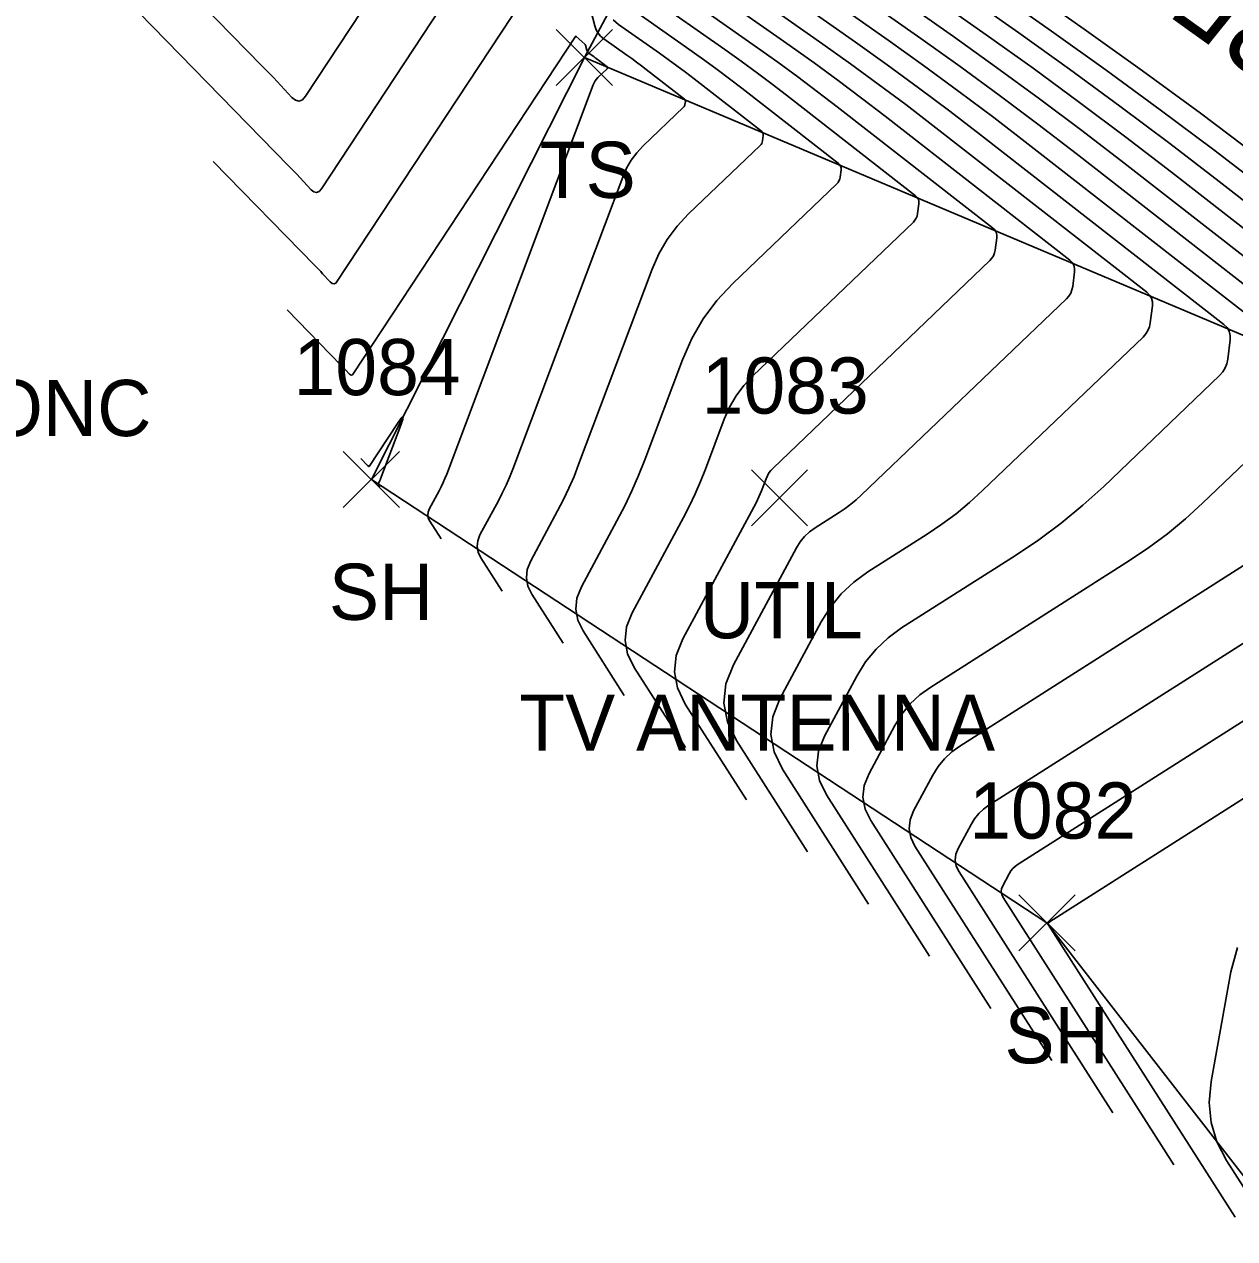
# Model space of a CAD drawing. Extents: x 1650836 to 1652450, y 332578 to 333908.
# Drawn here: x 1651814.49 to 1651857.58, y 332846.53 to 332889.77 of the extents above; entities that cross this region are included whole.
import ezdxf

# ---------------------------------------------------------------- set-up
doc = ezdxf.new("R2010")
doc.units = 0
for name, color, linetype in [('L_A', 7, 'Continuous'), ('L_I', 7, 'Continuous'), ('L_TIC', 7, 'Continuous'), ('LELB', 7, 'Continuous'), ('LSOGCMA', 7, 'Continuous'), ('LSOGCMA_T', 7, 'Continuous'), ('LSOGCMI', 7, 'Continuous'), ('LSOGP', 7, 'Continuous'), ('M_C', 7, 'Continuous'), ('U_A', 7, 'Continuous'), ('U_C', 7, 'Continuous'), ('U_I', 7, 'Continuous'), ('UDEFAULT', 7, 'Continuous')]:
    doc.layers.add(name, color=color, linetype=linetype)

msp = doc.modelspace()

# ---------------------------------------------------------------- linework, layer by layer
at = {"layer": 'L_TIC'}
for points in [[(1651833.429, 332887.588), (1651835.429, 332889.588)], [(1651835.429, 332887.588), (1651833.429, 332889.588)], [(1651825.845, 332872.564), (1651827.845, 332874.564)], [(1651827.845, 332872.564), (1651825.845, 332874.564)], [(1651849.897, 332856.776), (1651851.897, 332858.776)], [(1651851.897, 332856.776), (1651849.897, 332858.776)]]:
    msp.add_lwpolyline(points, dxfattribs=at)
at = {"layer": 'LELB'}
msp.add_lwpolyline([(1651981.067, 332787.388), (1651974.596, 332810.786), (1651972.976, 332830.46), (1651956.891, 332837.411), (1651913.583, 332855.638), (1651885.106, 332867.214), (1651834.429, 332888.588)], dxfattribs=at)
at = {"layer": 'LSOGCMA'}
for points in [[(1651839.894, 332893.845), (1651846.405, 332889.263), (1651847.805, 332888.264), (1651849.194, 332887.248), (1651850.569, 332886.216), (1651851.933, 332885.167), (1651862.682, 332876.792)], [(1651823.842, 332879.597), (1651825.773, 332877.621), (1651825.81, 332877.583), (1651825.847, 332877.544), (1651825.884, 332877.506), (1651825.92, 332877.467), (1651826.067, 332877.311), (1651826.102, 332877.283), (1651826.136, 332877.275), (1651826.168, 332877.288), (1651826.199, 332877.322), (1651834.107, 332889.333), (1651834.115, 332889.342), (1651834.123, 332889.345), (1651834.132, 332889.344), (1651834.141, 332889.337), (1651834.448, 332889.056), (1651834.455, 332889.049), (1651834.461, 332889.041), (1651834.465, 332889.033), (1651834.468, 332889.023), (1651834.514, 332888.845), (1651834.525, 332888.814), (1651834.54, 332888.786), (1651834.561, 332888.761), (1651834.586, 332888.74), (1651834.774, 332888.608), (1651834.814, 332888.579), (1651834.854, 332888.55), (1651834.894, 332888.52), (1651834.933, 332888.49), (1651835.243, 332888.248), (1651835.247, 332888.244), (1651835.25, 332888.239), (1651835.251, 332888.234), (1651835.251, 332888.228), (1651835.248, 332888.204), (1651835.247, 332888.198), (1651835.245, 332888.193), (1651835.242, 332888.188), (1651835.238, 332888.183), (1651834.909, 332887.868), (1651834.856, 332887.812), (1651834.81, 332887.75), (1651834.772, 332887.685), (1651834.741, 332887.614), (1651829.526, 332873.756), (1651829.466, 332873.603), (1651829.4, 332873.453), (1651829.33, 332873.304), (1651829.254, 332873.158), (1651828.905, 332872.51), (1651828.862, 332872.401), (1651828.85, 332872.292), (1651828.87, 332872.185), (1651828.922, 332872.079), (1651829.326, 332871.445)], [(1651857.899, 332870.496), (1651847.795, 332864.071), (1651847.506, 332863.86), (1651847.249, 332863.618), (1651847.026, 332863.345), (1651846.837, 332863.04), (1651846.148, 332861.76), (1651846.022, 332861.441), (1651845.988, 332861.126), (1651846.045, 332860.815), (1651846.195, 332860.506), (1651851.069, 332852.872)]]:
    msp.add_lwpolyline(points, dxfattribs=at)
at = {"layer": 'LSOGCMI'}
for points in [[(1651815.943, 332895.461), (1651822.951, 332888.29), (1651823.086, 332888.151), (1651823.221, 332888.011), (1651823.355, 332887.871), (1651823.488, 332887.73), (1651824.019, 332887.164), (1651824.149, 332887.061), (1651824.272, 332887.033), (1651824.388, 332887.082), (1651824.498, 332887.206), (1651830.857, 332896.863)], [(1651842.549, 332896.398), (1651852.22, 332889.59), (1651854.301, 332888.107), (1651856.363, 332886.598), (1651858.407, 332885.064)], [(1651842.018, 332895.887), (1651851.057, 332889.525), (1651853.002, 332888.138), (1651854.929, 332886.728), (1651856.84, 332885.295), (1651858.733, 332883.838)], [(1651841.487, 332895.377), (1651849.894, 332889.459), (1651851.703, 332888.17), (1651853.495, 332886.858), (1651855.272, 332885.525), (1651857.033, 332884.17), (1651870.913, 332873.356)], [(1651868.17, 332874.501), (1651855.333, 332884.503), (1651853.705, 332885.755), (1651852.061, 332886.988), (1651850.403, 332888.201), (1651848.731, 332889.394), (1651840.956, 332894.866)], [(1651831.94, 332894.353), (1651825.065, 332883.911), (1651824.982, 332883.817), (1651824.893, 332883.781), (1651824.8, 332883.802), (1651824.702, 332883.88), (1651824.299, 332884.309), (1651824.198, 332884.416), (1651824.096, 332884.522), (1651823.994, 332884.628), (1651823.892, 332884.733), (1651818.576, 332890.173)], [(1651865.426, 332875.647), (1651853.633, 332884.835), (1651852.137, 332885.986), (1651850.627, 332887.118), (1651849.104, 332888.232), (1651847.568, 332889.328), (1651840.425, 332894.356)], [(1651839.364, 332893.335), (1651845.241, 332889.197), (1651846.506, 332888.295), (1651847.76, 332887.379), (1651849.002, 332886.447), (1651850.233, 332885.499), (1651859.938, 332877.938)], [(1651846.72, 332856.586), (1651843.053, 332862.331), (1651842.803, 332862.845), (1651842.707, 332863.365), (1651842.764, 332863.89), (1651842.975, 332864.422), (1651844.125, 332866.558), (1651844.44, 332867.066), (1651844.812, 332867.521), (1651845.239, 332867.925), (1651845.723, 332868.277), (1651849.776, 332870.854), (1651850.607, 332871.412), (1651851.407, 332872.008), (1651852.177, 332872.643), (1651852.917, 332873.317), (1651857.043, 332877.268), (1651857.154, 332877.393), (1651857.24, 332877.532), (1651857.3, 332877.683), (1651857.335, 332877.847), (1651857.422, 332878.53), (1651857.424, 332878.693), (1651857.387, 332878.839), (1651857.31, 332878.97), (1651857.194, 332879.083), (1651848.533, 332885.832), (1651847.434, 332886.677), (1651846.326, 332887.509), (1651845.207, 332888.327), (1651844.078, 332889.132), (1651838.833, 332892.824)], [(1651844.546, 332858.444), (1651841.482, 332863.243), (1651841.182, 332863.86), (1651841.067, 332864.484), (1651841.136, 332865.115), (1651841.388, 332865.752), (1651842.863, 332868.492), (1651843.19, 332869.018), (1651843.574, 332869.49), (1651844.017, 332869.909), (1651844.518, 332870.273), (1651846.638, 332871.621), (1651847.159, 332871.97), (1651847.66, 332872.344), (1651848.143, 332872.741), (1651848.606, 332873.164), (1651854.317, 332878.632), (1651854.415, 332878.742), (1651854.491, 332878.864), (1651854.544, 332878.997), (1651854.574, 332879.142), (1651854.651, 332879.743), (1651854.653, 332879.886), (1651854.62, 332880.014), (1651854.552, 332880.129), (1651854.45, 332880.229), (1651846.833, 332886.164), (1651845.867, 332886.907), (1651844.892, 332887.639), (1651843.908, 332888.358), (1651842.915, 332889.066), (1651838.302, 332892.314)], [(1651833.024, 332891.843), (1651825.632, 332880.617), (1651825.575, 332880.553), (1651825.515, 332880.528), (1651825.451, 332880.542), (1651825.384, 332880.595), (1651825.11, 332880.888), (1651825.041, 332880.961), (1651824.972, 332881.033), (1651824.902, 332881.105), (1651824.832, 332881.177), (1651821.209, 332884.885)], [(1651842.372, 332860.301), (1651839.841, 332864.266), (1651839.518, 332864.93), (1651839.394, 332865.602), (1651839.468, 332866.282), (1651839.74, 332866.968), (1651841.977, 332871.125), (1651842.109, 332871.337), (1651842.264, 332871.528), (1651842.443, 332871.696), (1651842.645, 332871.843), (1651843.501, 332872.388), (1651843.711, 332872.528), (1651843.913, 332872.679), (1651844.108, 332872.84), (1651844.295, 332873.01), (1651851.591, 332879.996), (1651851.676, 332880.092), (1651851.741, 332880.197), (1651851.787, 332880.312), (1651851.813, 332880.436), (1651851.879, 332880.955), (1651851.881, 332881.078), (1651851.853, 332881.189), (1651851.794, 332881.288), (1651851.706, 332881.375), (1651845.133, 332886.496), (1651844.299, 332887.138), (1651843.458, 332887.769), (1651842.609, 332888.39), (1651841.752, 332889.001), (1651837.771, 332891.803)], [(1651840.197, 332862.158), (1651838.021, 332865.568), (1651837.743, 332866.139), (1651837.636, 332866.717), (1651837.7, 332867.301), (1651837.934, 332867.892), (1651840.541, 332872.735), (1651840.594, 332872.838), (1651840.644, 332872.943), (1651840.69, 332873.049), (1651840.732, 332873.157), (1651840.896, 332873.591), (1651840.942, 332873.696), (1651840.999, 332873.794), (1651841.067, 332873.885), (1651841.145, 332873.968), (1651848.866, 332881.361), (1651848.937, 332881.441), (1651848.992, 332881.529), (1651849.03, 332881.626), (1651849.052, 332881.731), (1651849.108, 332882.167), (1651849.109, 332882.271), (1651849.086, 332882.364), (1651849.037, 332882.447), (1651848.963, 332882.52), (1651843.433, 332886.828), (1651842.732, 332887.368), (1651842.024, 332887.899), (1651841.31, 332888.421), (1651840.589, 332888.935), (1651837.24, 332891.292)], [(1651836.71, 332890.782), (1651839.426, 332888.87), (1651840.011, 332888.453), (1651840.59, 332888.029), (1651841.164, 332887.598), (1651841.733, 332887.161), (1651846.219, 332883.666), (1651846.279, 332883.607), (1651846.319, 332883.539), (1651846.338, 332883.464), (1651846.337, 332883.379), (1651846.292, 332883.026), (1651846.274, 332882.94), (1651846.242, 332882.862), (1651846.198, 332882.79), (1651846.14, 332882.725), (1651840.427, 332877.255), (1651840.106, 332876.912), (1651839.829, 332876.54), (1651839.596, 332876.139), (1651839.406, 332875.709), (1651838.737, 332873.93), (1651838.563, 332873.489), (1651838.374, 332873.054), (1651838.17, 332872.626), (1651837.952, 332872.204), (1651836.128, 332868.816), (1651835.932, 332868.321), (1651835.879, 332867.832), (1651835.969, 332867.349), (1651836.201, 332866.87), (1651838.023, 332864.016)], [(1651831.5, 332869.588), (1651830.741, 332870.777), (1651830.645, 332870.976), (1651830.607, 332871.177), (1651830.63, 332871.381), (1651830.711, 332871.587), (1651831.366, 332872.803), (1651831.507, 332873.077), (1651831.639, 332873.355), (1651831.762, 332873.637), (1651831.876, 332873.924), (1651835.792, 332884.331), (1651835.928, 332884.64), (1651836.095, 332884.928), (1651836.294, 332885.195), (1651836.525, 332885.441), (1651837.963, 332886.819), (1651837.981, 332886.838), (1651837.994, 332886.86), (1651838.004, 332886.884), (1651838.009, 332886.909), (1651838.023, 332887.016), (1651838.023, 332887.042), (1651838.017, 332887.064), (1651838.005, 332887.085), (1651837.987, 332887.103), (1651836.633, 332888.157), (1651836.462, 332888.289), (1651836.288, 332888.419), (1651836.113, 332888.547), (1651835.937, 332888.673), (1651835.117, 332889.25), (1651835.006, 332889.343), (1651834.916, 332889.451), (1651834.848, 332889.573), (1651834.8, 332889.71), (1651834.601, 332890.489)], [(1651833.675, 332867.73), (1651832.561, 332869.474), (1651832.419, 332869.767), (1651832.365, 332870.062), (1651832.397, 332870.361), (1651832.517, 332870.663), (1651833.477, 332872.447), (1651833.685, 332872.849), (1651833.879, 332873.257), (1651834.059, 332873.671), (1651834.225, 332874.092), (1651836.843, 332881.049), (1651837.084, 332881.596), (1651837.38, 332882.105), (1651837.733, 332882.578), (1651838.141, 332883.014), (1651840.689, 332885.454), (1651840.72, 332885.489), (1651840.744, 332885.527), (1651840.76, 332885.569), (1651840.77, 332885.615), (1651840.794, 332885.804), (1651840.795, 332885.849), (1651840.784, 332885.889), (1651840.763, 332885.925), (1651840.731, 332885.957), (1651838.333, 332887.825), (1651838.029, 332888.059), (1651837.722, 332888.289), (1651837.413, 332888.516), (1651837.1, 332888.739), (1651835.648, 332889.761), (1651835.451, 332889.925)], [(1651836.179, 332890.271), (1651838.263, 332888.804), (1651838.712, 332888.484), (1651839.156, 332888.159), (1651839.597, 332887.829), (1651840.033, 332887.493), (1651843.475, 332884.811), (1651843.521, 332884.766), (1651843.551, 332884.714), (1651843.566, 332884.656), (1651843.565, 332884.592), (1651843.531, 332884.32), (1651843.517, 332884.255), (1651843.493, 332884.195), (1651843.459, 332884.14), (1651843.415, 332884.09), (1651839.71, 332880.543), (1651839.146, 332879.94), (1651838.659, 332879.287), (1651838.25, 332878.583), (1651837.917, 332877.827), (1651836.575, 332874.26), (1651836.356, 332873.706), (1651836.118, 332873.159), (1651835.863, 332872.621), (1651835.589, 332872.092), (1651834.323, 332869.739), (1651834.165, 332869.341), (1651834.122, 332868.947), (1651834.194, 332868.558), (1651834.381, 332868.172), (1651835.849, 332865.873)], [(1651826.475, 332874.309), (1651826.713, 332874.065), (1651826.727, 332874.051), (1651826.749, 332874.027), (1651826.754, 332874.023), (1651826.758, 332874.022), (1651826.762, 332874.024), (1651826.766, 332874.028), (1651827.773, 332875.557), (1651827.907, 332875.746), (1651827.972, 332875.799), (1651827.968, 332875.715), (1651827.894, 332875.495), (1651827.176, 332873.588), (1651827.169, 332873.569), (1651827.161, 332873.55), (1651827.152, 332873.532), (1651827.143, 332873.514), (1651827.1, 332873.434), (1651827.094, 332873.421), (1651827.093, 332873.407), (1651827.095, 332873.394), (1651827.102, 332873.381), (1651827.152, 332873.303)], [(1651859.768, 332875.903), (1651856.44, 332872.717), (1651855.826, 332872.157), (1651855.187, 332871.63), (1651854.523, 332871.135), (1651853.833, 332870.672), (1651846.759, 332866.174), (1651846.372, 332865.893), (1651846.03, 332865.57), (1651845.733, 332865.205), (1651845.481, 332864.799), (1651844.562, 332863.091), (1651844.393, 332862.666), (1651844.347, 332862.246), (1651844.424, 332861.83), (1651844.624, 332861.419), (1651848.895, 332854.729)], [(1651853.243, 332851.014), (1651847.766, 332859.594), (1651847.666, 332859.799), (1651847.628, 332860.007), (1651847.651, 332860.217), (1651847.735, 332860.429), (1651848.194, 332861.281), (1651848.32, 332861.484), (1651848.468, 332861.666), (1651848.639, 332861.827), (1651848.832, 332861.968), (1651861.965, 332870.32)], [(1651855.417, 332849.157), (1651849.337, 332858.682), (1651849.287, 332858.784), (1651849.268, 332858.888), (1651849.279, 332858.992), (1651849.321, 332859.098), (1651849.55, 332859.523), (1651849.613, 332859.624), (1651849.687, 332859.714), (1651849.772, 332859.795), (1651849.868, 332859.865), (1651866.031, 332870.143)], [(1651870.097, 332869.967), (1651851.136, 332857.909), (1651851.116, 332857.896), (1651851.097, 332857.883), (1651851.077, 332857.87), (1651851.058, 332857.857), (1651850.953, 332857.783), (1651850.949, 332857.779), (1651850.945, 332857.775), (1651850.943, 332857.77), (1651850.941, 332857.764), (1651850.937, 332857.74), (1651850.936, 332857.734), (1651850.937, 332857.728), (1651850.938, 332857.723), (1651850.941, 332857.718), (1651857.592, 332847.3)], [(1651857.684, 332856.896), (1651857.446, 332856.039), (1651856.737, 332852.124), (1651856.67, 332851.383), (1651856.739, 332850.669), (1651856.946, 332849.981), (1651857.29, 332849.321), (1651859.766, 332845.442)]]:
    msp.add_lwpolyline(points, dxfattribs=at)
at = {"layer": 'LSOGP'}
msp.add_lwpolyline([(1651814.272, 332938.956), (1651818.842, 332935.985), (1651823.411, 332933.014), (1651827.981, 332930.043), (1651832.551, 332927.072), (1651837.12, 332924.1), (1651841.69, 332921.129), (1651846.26, 332918.158), (1651844.759, 332915.941), (1651847.527, 332911.35), (1651845.231, 332908.813), (1651834.429, 332888.588), (1651826.845, 332873.564), (1651850.897, 332857.776), (1651861.906, 332843.614), (1651887.79, 332823.882), (1651895.345, 332817.735), (1651915.287, 332808.731), (1651939.148, 332804.133), (1651956.389, 332793.224), (1651973.519, 332785.08), (1651977.172, 332765.646), (1651984.523, 332752.343)], dxfattribs=at)
at = {"layer": 'UDEFAULT'}
for points in [[(1651840.377, 332871.907), (1651842.377, 332873.907)], [(1651842.377, 332871.907), (1651840.377, 332873.907)]]:
    msp.add_lwpolyline(points, dxfattribs=at)

# ---------------------------------------------------------------- texts
at = {"layer": 'L_A'}
for s, p in [('TS', (1651832.838, 332883.588)), ('SH', (1651825.334, 332868.564)), ('SH', (1651849.385, 332852.776))]:
    msp.add_text(s, height=2, dxfattribs=at).set_placement(p)
at = {"layer": 'L_I'}
for s, p in [('1084', (1651824.074, 332876.564)), ('1082', (1651848.126, 332860.776))]:
    msp.add_text(s, height=2, dxfattribs=at).set_placement(p)
at = {"layer": 'LSOGCMA_T'}
msp.add_text('835', height=3, rotation=144.3842, dxfattribs=at).set_placement((1651862.292, 332888.687))
at = {"layer": 'M_C'}
msp.add_text('VTHD CONC', height=2, dxfattribs=at).set_placement((1651803.116, 332875.107))
at = {"layer": 'U_A'}
msp.add_text('UTIL', height=2, dxfattribs=at).set_placement((1651838.542, 332867.907))
at = {"layer": 'U_C'}
msp.add_text('TV ANTENNA', height=2, dxfattribs=at).set_placement((1651832.109, 332863.907))
at = {"layer": 'U_I'}
msp.add_text('1083', height=2, dxfattribs=at).set_placement((1651838.605, 332875.907))

doc.saveas('drawing.dxf')
